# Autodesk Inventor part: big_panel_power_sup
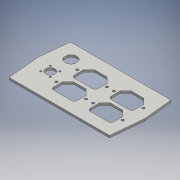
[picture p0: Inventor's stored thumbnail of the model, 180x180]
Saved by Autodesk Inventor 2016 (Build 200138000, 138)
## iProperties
Created: 2016-12
Part Number: big_panel_power_sup
Material: Типовые
Document SubType Name: Modeling
Designer: admin
Density: 1 g/cm^3
Appearance: По умолчанию
Author: admin
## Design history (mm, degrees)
sketch "Эскиз1"
  geometry: L1 (-68, -41.5)-(68, -41.5); L2 (68, 41.5)-(-68, 41.5); L3 (-68, 41.5)-(-72, 2); L4 (-72, 2)-(-68, -41.5); L5 (68, 41.5)-(72, 2); L6 (72, 2)-(68, -41.5); 2 further points
  constraints: 12 end point, 1 horizontal, 1 midpoint, 1 parallel, 1 vertical alignment
extrude "Выдавливание1" new body sketch "Эскиз1" distance "d20" = 3; taper "d21" = 0 deg
sketch "Эскиз4"
  geometry: L1 (30.426, -2.9)-(47.426, -2.9); L2 (54.926, -10.4)-(54.926, -22.5); L3 (50.926, -26.5)-(26.926, -26.5); L4 (22.926, -22.5)-(22.926, -10.4); L5 (22.926, -2.9)-(54.926, -26.5); L6 (22.926, -26.5)-(54.926, -2.9); L7 (14.176, -28.75)-(63.676, -28.75); L8 (63.676, -28.75)-(63.676, -0.65); L9 (63.676, -0.65)-(14.176, -0.65); L10 (14.176, -0.65)-(14.176, -28.75); L11 (14.176, -28.75)-(63.676, -0.65); L12 (63.676, -28.75)-(14.176, -0.65); L13 (22.926, -10.4)-(30.426, -2.9); L14 (54.926, -10.4)-(47.426, -2.9); L15 (30.426, 25.3)-(47.426, 25.3); L16 (50.926, 1.7)-(26.926, 1.7); L17 (22.926, 25.3)-(54.926, 1.7); L18 (22.926, 1.7)-(54.926, 25.3); L19 (14.176, -0.55)-(63.676, -0.55); L20 (63.676, -0.55)-(14.176, 27.55); L21 (14.176, -0.55)-(63.676, 27.55); L22 (63.676, 27.55)-(14.176, 27.55); L23 (22.926, 17.8)-(30.426, 25.3); L24 (22.926, 5.7)-(22.926, 17.8); L25 (14.176, 27.55)-(14.176, -0.55); L26 (54.926, 17.8)-(54.926, 5.7); L27 (54.926, 17.8)-(47.426, 25.3); L28 (63.676, -0.55)-(63.676, 27.55); L29 (-19.174, 25.3)-(-2.174, 25.3); L30 (1.326, 1.7)-(-22.674, 1.7); L31 (-26.674, 25.3)-(5.326, 1.7); L32 (-26.674, 1.7)-(5.326, 25.3); L33 (-35.424, -0.55)-(14.076, -0.55); L34 (14.076, -0.55)-(-35.424, 27.55); L35 (-35.424, -0.55)-(14.076, 27.55); L36 (14.076, 27.55)-(-35.424, 27.55); L37 (-26.674, 17.8)-(-19.174, 25.3); L38 (-26.674, 5.7)-(-26.674, 17.8); L39 (-35.424, 27.55)-(-35.424, -0.55); L40 (5.326, 17.8)-(5.326, 5.7); L41 (5.326, 17.8)-(-2.174, 25.3); L42 (14.076, -0.55)-(14.076, 27.55); L43 (-19.174, -2.9)-(-2.174, -2.9); L44 (1.326, -26.5)-(-22.674, -26.5); L45 (-26.674, -2.9)-(5.326, -26.5); L46 (-26.674, -26.5)-(5.326, -2.9); L47 (-35.424, -28.75)-(14.076, -28.75); L48 (14.076, -28.75)-(-35.424, -0.65); L49 (-35.424, -28.75)-(14.076, -0.65); L50 (14.076, -0.65)-(-35.424, -0.65); L51 (-26.674, -10.4)-(-19.174, -2.9); L52 (-26.674, -22.5)-(-26.674, -10.4); L53 (-35.424, -0.65)-(-35.424, -28.75); L54 (5.326, -10.4)-(5.326, -22.5); L55 (5.326, -10.4)-(-2.174, -2.9); L56 (14.076, -28.75)-(14.076, -0.65); L57 (-56.279, -15.5)-(-38.279, -15.5); L58 (-38.279, -15.5)-(-38.279, 2.5); L59 (-38.279, 2.5)-(-56.279, 2.5); L60 (-56.279, 2.5)-(-56.279, -15.5); L61 (-56.279, -15.5)-(-38.279, 2.5); L62 (-38.279, -15.5)-(-56.279, 2.5); L63 (-53.779, -13)-(-40.779, -13); L64 (-40.779, -13)-(-40.779, 0)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; C1 r 1.25 at (-53.779, 0); C2 r 1.25 at (-40.779, 0); C3 r 1.25 at (-53.779, -13); C4 r 1.25 at (-40.779, -13); C5 r 6.25 at (-47.279, -6.5); C6 r 10.5 at (-47.279, 21.5); C7 r 1.75 at (-30.674, 13.5); C8 r 1.75 at (9.326, 13.5); C9 r 1.75 at (-30.674, -14.7); C10 r 1.75 at (9.326, -14.7); C11 r 1.75 at (18.926, 13.5); C12 r 1.75 at (58.926, 13.5); C13 r 1.75 at (18.926, -14.7); C14 r 1.75 at (58.926, -14.7); A1 r 4 centre (26.926, -22.5) between (22.926, -22.5) and (26.926, -26.5); A2 r 4 centre (50.926, -22.5) between (50.926, -26.5) and (54.926, -22.5); A3 r 4 centre (26.926, 5.7) between (22.926, 5.7) and (26.926, 1.7); A4 r 4 centre (50.926, 5.7) between (50.926, 1.7) and (54.926, 5.7); A5 r 4 centre (-22.674, 5.7) between (-26.674, 5.7) and (-22.674, 1.7); A6 r 4 centre (1.326, 5.7) between (1.326, 1.7) and (5.326, 5.7); A7 r 4 centre (-22.674, -22.5) between (-26.674, -22.5) and (-22.674, -26.5); A8 r 4 centre (1.326, -22.5) between (1.326, -26.5) and (5.326, -22.5); A9 r 7.8 centre (-47.279, 21.5) between (-54.629, 18.889) and (-39.929, 18.889); A10 r 7.8 centre (-47.279, 21.5) between (-39.929, 24.111) and (-54.629, 24.111); 17 further points
  constraints: 164 end point, 34 point on line, 26 midpoint, 24 centre point, 22 parallel, 20 point on circle, 17 horizontal, 16 tangent, 12 coincident, 11 perpendicular, 4 equal radius, 3 vertical, 1 horizontal alignment
  dimensions: "d56" = 49.5 distance of L9.end L8.end; "d57" = 28.1 distance of L8.end L7.end; "d58" = 32 distance of L5.start L6.end; "d59" = 23.6 distance of L6.end L5.end; "d60" = 7.5 distance of L4.end L5.start; "d61" = 7.5 distance of L1.start L5.start (= d60); "d62" = 7.5 distance of L2.start L6.end; "d63" = 7.5 distance of L1.end L6.end (= d62); "d64" = 4 radius of A1; "d65" = 49.5 distance of L20.end L21.end; "d66" = 28.1 distance of L21.end L19.end; "d67" = 32 distance of L17.start L18.end; "d68" = 23.6 distance of L18.end L17.end; "d69" = 7.5 distance of L23.start L17.start; "d70" = 7.5 distance of L15.start L17.start (= d69); "d71" = 7.5 distance of L26.start L18.end; "d72" = 7.5 distance of L15.end L18.end (= d71); "d73" = 4 radius of A3; "d74" = 49.5 distance of L34.end L35.end; "d75" = 28.1 distance of L35.end L33.end; "d76" = 32 distance of L31.start L32.end; "d77" = 23.6 distance of L32.end L31.end; "d78" = 7.5 distance of L37.start L31.start; "d79" = 7.5 distance of L29.start L31.start (= d78); "d80" = 7.5 distance of L40.start L32.end; "d81" = 7.5 distance of L29.end L32.end (= d80); "d82" = 4 radius of A5; "d83" = 49.5 distance of L48.end L49.end; "d84" = 28.1 distance of L49.end L47.end; "d85" = 32 distance of L45.start L46.end; "d86" = 23.6 distance of L46.end L45.end; "d87" = 7.5 distance of L51.start L45.start; "d88" = 7.5 distance of L43.start L45.start (= d87); "d89" = 7.5 distance of L54.start L46.end; "d90" = 7.5 distance of L43.end L46.end (= d89); "d91" = 4 radius of A7; "d92" = 18 distance of L59.end L58.end; "d93" = 18 distance of L58.end L57.end; "d94" = 13 distance of L65.end L64.end; "d95" = 13 distance of L64.end L63.end; "d96" = 2.5 diameter of C1; "d97" = 2.5 diameter of C2; "d98" = 2.5 diameter of C3; "d99" = 2.5 diameter of C4; "d100" = 12.5 diameter of C5; "d104" = 7.8 radius of A10; "d105" = 7.8 radius of A9; "d106" = 14.7 distance between parallel lines of L69 L70; "d107" = 5.22207 distance of L69.start L69.end; "d108" = 21 diameter of C6; "d109" = 17 distance of L75.start L75.end; "d110" = 17 distance of L76.start L76.end; "d111" = 15 distance between parallel lines of L3 L81; "d112" = 0.1 distance between parallel lines of L19 L9; "d113" = 0.1 distance between parallel lines of L10 L56; "d114" = 0.1 distance between parallel lines of L50 L33; "d116" = 35 distance from line of point (-47.279, -6.5) L81; "d117" = 20 distance from line of C6.centre L82; "d118" = 3.5 diameter of C7; "d119" = 3.5 diameter of C8; "d120" = 40 distance of L83.end L83.start; "d121" = 3.5 diameter of C9; "d122" = 3.5 diameter of C10; "d123" = 40 distance of L84.end L84.start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
extrude "Выдавливание4" cut sketch "Эскиз4" distance "d130" = 10; taper "d131" = 0 deg
node "Твердое тело1"
other parameters: "d34" = 77
